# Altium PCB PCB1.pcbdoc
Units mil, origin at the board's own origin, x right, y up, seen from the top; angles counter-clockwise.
Board outline 14460 x 8445 mil, 2 copper layers (Top Layer, Bottom Layer); 15 components, 13 nets, 44 pads, 9 vias.
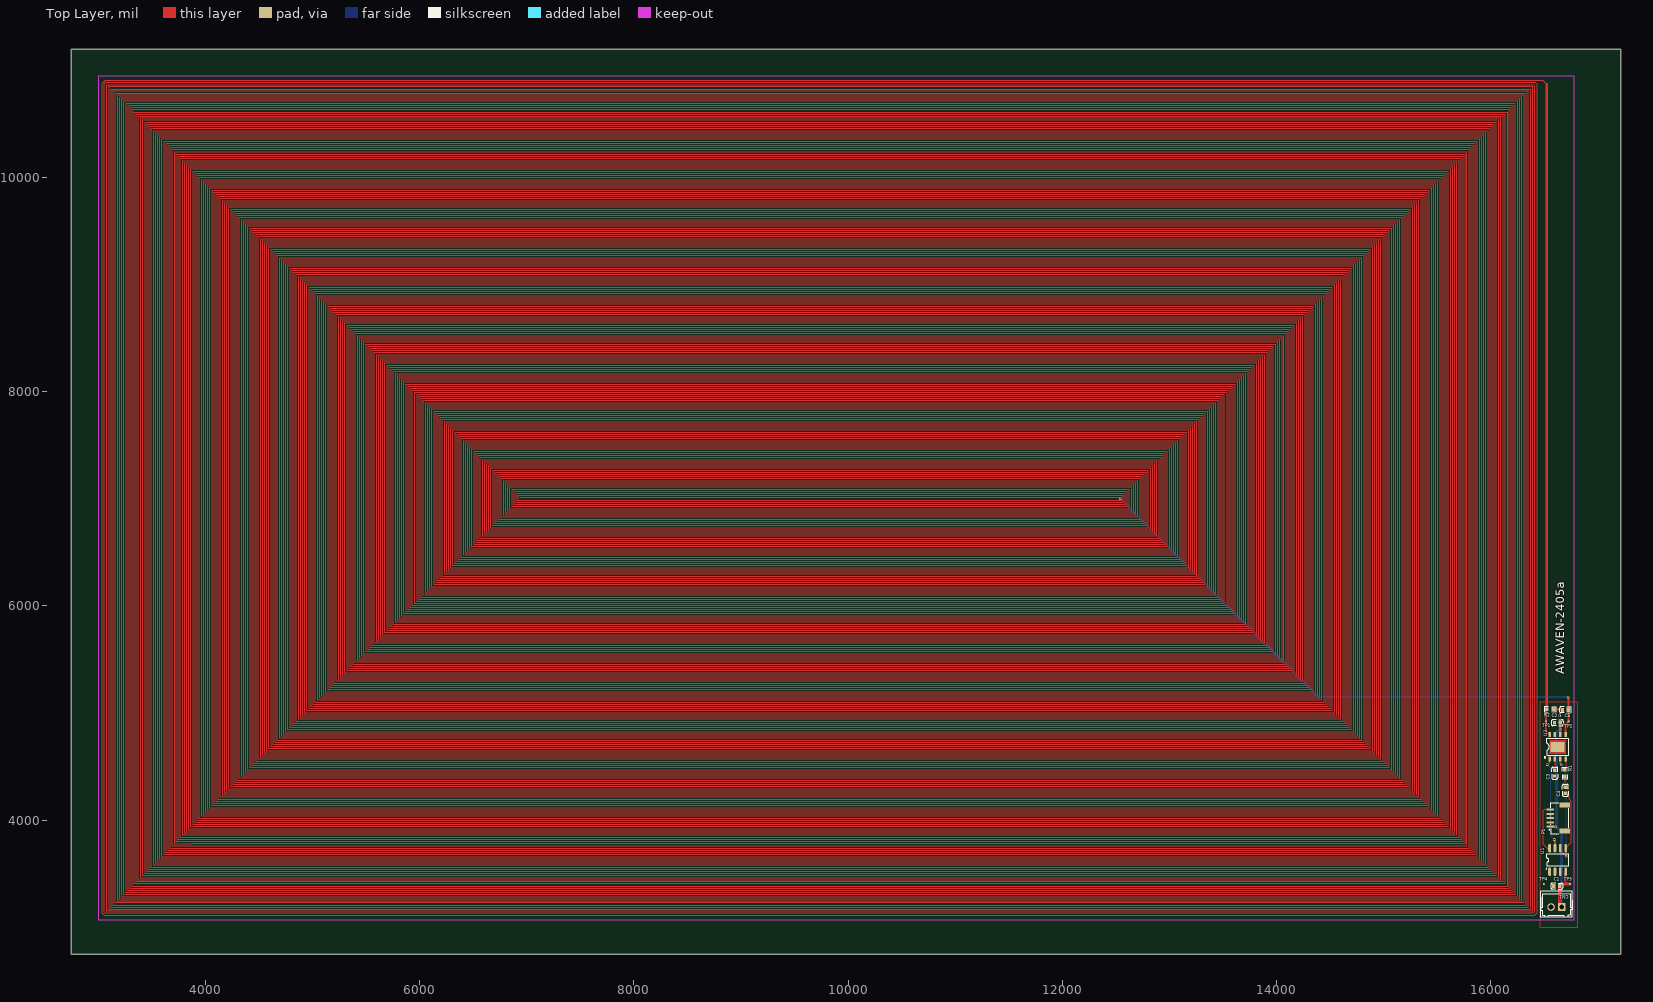
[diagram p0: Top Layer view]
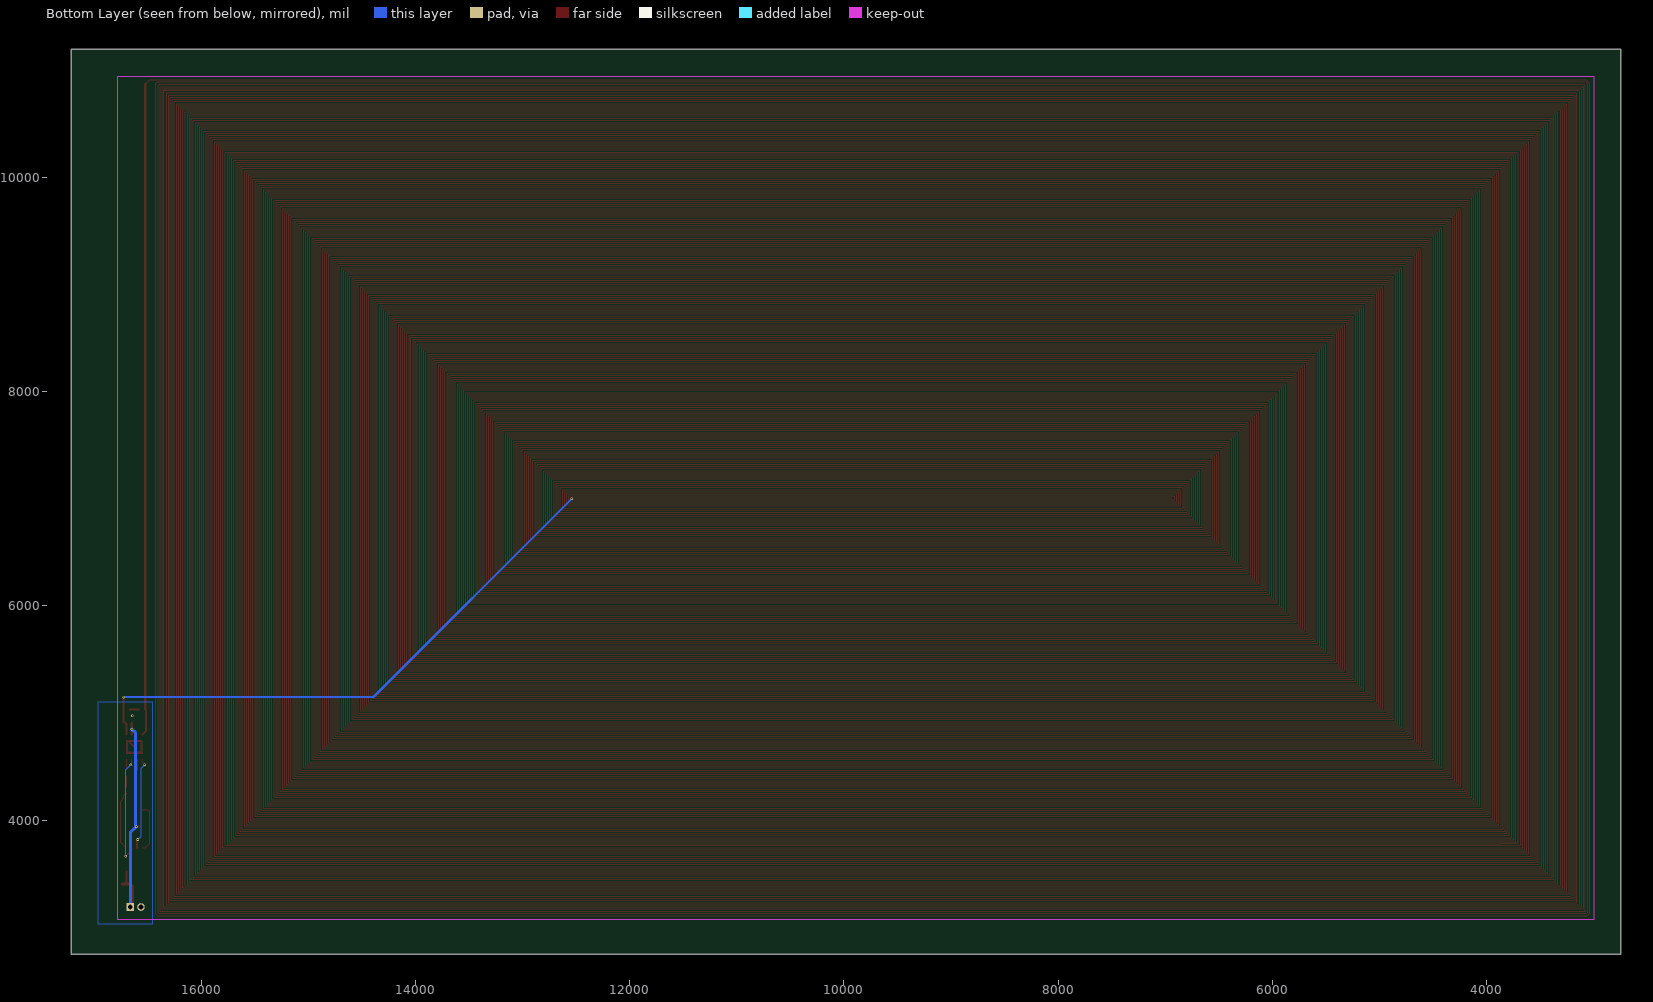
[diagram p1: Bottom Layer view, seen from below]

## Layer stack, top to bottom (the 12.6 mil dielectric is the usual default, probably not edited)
Top Layer: signal copper (thickness not stored)
Dielectric: dielectric 12.6, FR-4, Dk 4.8
Bottom Layer: signal copper (thickness not stored)

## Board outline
17210,2750 2750,2750 2750,11195 17210,11195

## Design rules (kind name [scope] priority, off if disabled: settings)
Clearance copperThickness1oz [All] p1: gap=7 ignorepadtopadclearanceinfootprint=FALSE except(4: Track-Track; 6: Track-SMDPad SMDPad-SMDPad Track-THPad SMDPad-THPad THPad-THPad Track-Via SMDPad-Via THPad-Via Via-Via Track-Fill SMDPad-Fill THPad-Fill Via-Fill Fill-Fill SMDPad-Region THPad-Region Via-Region Fill-Region Region-Region Track-Poly SMDPad-Poly THPad-Poly Via-Poly Fill-Poly Poly-Poly Track-Text SMDPad-Text THPad-Text Via-Text Fill-Text Region-Text Poly-Text Text-Text Track-Hole SMDPad-Hole THPad-Hole Via-Hole Fill-Hole Region-Hole Poly-Hole Text-Hole; 11.8: Track-Region Region-Poly Track-Sheet SMDPad-Sheet THPad-Sheet Via-Sheet Fill-Sheet Region-Sheet Poly-Sheet Text-Sheet Sheet-Hole)
Clearance copperThickness2oz [All] p1: gap=7 ignorepadtopadclearanceinfootprint=FALSE except(6: Track-SMDPad SMDPad-SMDPad Track-THPad SMDPad-THPad THPad-THPad Track-Via SMDPad-Via THPad-Via Via-Via Track-Fill SMDPad-Fill THPad-Fill Via-Fill Fill-Fill SMDPad-Region THPad-Region Via-Region Fill-Region Region-Region Track-Poly SMDPad-Poly THPad-Poly Via-Poly Fill-Poly Poly-Poly Track-Text SMDPad-Text THPad-Text Via-Text Fill-Text Region-Text Poly-Text Text-Text Track-Hole SMDPad-Hole THPad-Hole Via-Hole Fill-Hole Region-Hole Poly-Hole Text-Hole; 8: Track-Track; 11.8: Track-Region Region-Poly Track-Sheet SMDPad-Sheet THPad-Sheet Via-Sheet Fill-Sheet Region-Sheet Poly-Sheet Text-Sheet Sheet-Hole)
DiffPairsRouting differentialPair [All] p1: maxuncoupledlength=10 minlimit=0 maxlimit=5.9843 mostfreqgap=5.9843 toplayer_minwidth=5 toplayer_prefwidth=10 toplayer_maxwidth=100 bottomlayer_minwidth=5 bottomlayer_prefwidth=10 bottomlayer_maxwidth=100
PasteMaskExpansion pasteMaskExpansion [All] p1: expansion=0
PlaneConnect innerPlane [All] p1: planeconnectstyle=Relief reliefexpansion=20 reliefentries=4 reliefconductorwidth=10 reliefairgap=10
PolygonConnect copperRegion [All] p1: connectstyle=Relief reliefentries=4 reliefconductorwidth=10 polygonreliefangle="90 Angle" airgapwidth=10
RoutingVias viaSize [All] p1: viastyle="Through Hole" holewidth=12.0078 minholewidth=11.811 maxholewidth=248.0314 width=24.0158 minwidth=19.685 maxwidth=393.7008
SolderMaskExpansion solderMaskExpansion [All] p1: useseparateexpansions=TRUE expansion=2.0079 expansionbottom=2.0079
Width copperThickness1oz [All] p1: maxlimit=100 minlimit=5 preferedwidth=10
Width copperThickness2oz [All] p1: maxlimit=100 minlimit=8 preferedwidth=10

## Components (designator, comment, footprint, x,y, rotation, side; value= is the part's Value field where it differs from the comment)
C1 "0603B104K500NT" C0603 16615,3385 r0 top
C2 "CAP_0603" C0603 16620,4910 r0 top
C3 "CAP_0603" C0603 16595,4440 r90 top
C4 "CAP_0603" C0603 16695,4280 r90 top
C5 "CAP_0603" C0603 16695,5030 r180 top
CN1 "ZX-XH2.54-2PZZ" CONN-TH_2P-P2.50_HX25003-2A 16610,3190 r180 top
P1 "ZX-SH1.0-5PWT" CONN-SMD_5P-P1.00_MEGASTAR_ZX-SH1.0-5PWT 16620,4020 r90 top
R1 "Res_0603" R0603 16690,4440 r270 top
R2 "Res_0603" R0603 16550,5035 r180 top
TP1 "Test-Point" Test-Point-0.5mm 16515.08,4921.38 r0 top
TP2 "Test-Point" Test-Point-0.5mm 16725.08,4921.38 r0 top
TP3 "Test-Point" Test-Point-0.5mm 16738.16,3405.63 r0 top
TP4 "Test-Point" Test-Point-0.5mm 16493.3,3405.63 r0 top
U1 "CH32V003J4M6_C5346354" SOP-8_L4.9-W3.8-P1.27-LS6.0-BL 16622.05,3630 r0 top
U2 "LTK5128D" ESOP-8_L4.9-W3.9-P1.27-LS6.0-BL-EP 16622.05,4685 r0 top

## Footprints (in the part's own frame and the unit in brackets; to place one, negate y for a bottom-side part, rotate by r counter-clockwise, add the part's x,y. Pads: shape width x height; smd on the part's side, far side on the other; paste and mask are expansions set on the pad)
C0603 [mm]
  rect 0.8x0.9 smd: 1(-0.7,0) 2(0.7,0)
  silkscreen extent -1.41,-0.71 1.39,0.72
CONN-SMD_5P-P1.00_MEGASTAR_ZX-SH1.0-5PWT [mm]
  rect 0.5x1.7 smd: 1(-2,1.7) 2(-1,1.7) 3(0,1.7) 4(1,1.7) 5(2,1.7)
  rect 1.2x2.5 smd: 6(3.1,-1.7) 7(-3.1,-1.7)
  silkscreen extent -3.67,-2.7 3.68,2.21
CONN-TH_2P-P2.50_HX25003-2A [mm]
  rect 1.8x1.8 hole 1.1: 1(-1.25,0)
  round 1.8 hole 1.1: 2(1.25,0)
  silkscreen extent -3.75,-3.7 3.75,2.41
ESOP-8_L4.9-W3.9-P1.27-LS6.0-BL-EP [mm]
  rect 0.6x1.2 smd: 1(-1.905,-2.908) 2(-0.635,-2.908) 3(0.635,-2.908) 4(1.905,-2.908) 5(1.905,2.908) 6(0.635,2.908) 7(-0.635,2.908) 8(-1.905,2.908)
  rect 3.3x2.4 smd: 9(0,0)
  silkscreen extent -3.2,-2.67 2.55,2.05
R0603 [mil]
  rect 31.75x34.02 smd: 1(-29.66,0) 2(29.66,0)
  silkscreen extent -55,-26 55,26
SOP-8_L4.9-W3.8-P1.27-LS6.0-BL [mil]
  oval 25.59x80 smd: 1(-75,-110.08) 2(-25,-110.08) 3(25,-110.08) 4(75,-110.08) 5(75,110.08) 6(25,110.08) 7(-25,110.08) 8(-75,110.08)
  silkscreen extent -108,-85 101,57
Test-Point-0.5mm [mm]
  round 0.5 smd: 1(0,0)

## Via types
v1: diameter 24.02, hole 12.01, Top Layer to Bottom Layer, 9 vias

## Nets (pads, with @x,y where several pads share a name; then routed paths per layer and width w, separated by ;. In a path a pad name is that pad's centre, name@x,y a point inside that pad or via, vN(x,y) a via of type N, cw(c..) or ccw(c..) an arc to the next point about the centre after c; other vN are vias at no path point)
$1N468: C3.2 U2.2 | length 103.8
  Top Layer w10: C3.2 16597.05,4469.61 U2.2
$1N596: C4.1 U1.5 | length 557.1
  Top Layer w10: C4.1 16725,4222.44 16725,4203.7 16750,4178.7 16750,3793.03 U1.5
$1N669: C4.2 R1.2 | length 104.9
  Top Layer w10: R1.2 16695,4405.34 C4.2
$1N795: C5.2 R2.1 | length 89.9
  Top Layer w19.68: R2.1 16662.44,5035 C5.2
DIO: P1.5 U1.8 | length 459.5
  Top Layer w10: U1.8 16524.92,3740.08 16485,3780 16485,4088.74 16495,4098.74 P1.5
GND: C1.1 C2.1 C3.1 CN1.2 P1.4 P1.6 P1.7 TP4.1 U1.2 U2.7 U2.9 | length 571.1
  Top Layer w19.68: U2.9 16675,4737.95 16675,4740 16555,4740 16555,4635 16550,4630 16685,4630 16690,4625 16690,4745
  other v1: 16640,4975
IN: R1.1 U2.4 | length 103.8
  Top Layer w10: R1.1 16697.05,4476.71 U2.4
MODE: U1.6 U2.3 | length 1028.3
  Top Layer w10: U1.6 16647.05,3718.62 v1(16701.83,3663.84) ; U2.3 16647.05,4525.3 v1(16656.14,4516.21)
  Bottom Layer w10: v1(16656.14,4516.21) 16701.83,4470.52 v1(16701.83,3663.84)
OV: C5.1 R2.2 TP1.1 TP2.1 U2.5 U2.8 | length 5333328.9
  Top Layer w10: 3070,3130 3059.06,3140.94 3059.06,10874.06 3070.94,10885.94 16415,10885.94 ; 3070.04,3130.04 16391.66,3130.04 16405,3143.38 ; 3098.43,3169.41 16365,3169.41 ; 3098.43,3175 3098.43,10846.57 16384.25,10846.57 16385.83,10845 16385.83,3150 3080,3150 3080,10860 3085,10865 16396.8,10865 16405.51,10856.29 16405.51,3143.38 ; 3137.8,3208.78 16325,3208.78 ; 3137.8,3210 3137.8,10803.19 3141.81,10807.2 16346.46,10807.2 16346.46,3190 3118.11,3190 3118.11,10825 16366.14,10825 16366.14,3169.41 ; 3157.48,3228.46 3157.48,10785 3160,10787.52 16326.77,10787.52 ; 3160,3228.46 16305,3228.46 ; 3177.17,10767.83 3177.17,3248.15 16285,3248.15 ; 3180,10767.83 16303.86,10767.83 16306.69,10765 16306.69,3228.46 ; 3196.85,10748.15 3196.85,3267.83 16265,3267.83 ; 3200,10748.15 16287.4,10748.15 16287.4,3248.15 ; 3236.22,3307.2 16228.35,3307.2 16228.35,10689.09 3255.91,10689.09 3255.91,3326.89 16208.66,3326.89 16208.66,10668.66 ; 3236.22,3308.78 3236.22,10709.17 16248.03,10709.17 16248.03,3287.52 ; 3275.59,3346.57 16188.98,3346.57 16188.98,10649.72 ; 3275.59,3350 3275.59,10669.41 16208.66,10669.41 ; 3295,10649.72 3295.28,10649.72 ; 3374.02,10570.98 3374.02,3445.98 3375,3445 16090.55,3445 16090.55,10551.3 3393.7,10551.3 3393.7,3465 ; 3375,10570.98 16110.24,10570.98 16110.24,3425.32 3354.33,3425.32 3354.33,10590.67 16129.92,10590.67 16129.92,3405.63 3334.65,3405.63 3334.65,10610.35 16149.61,10610.35 16149.61,3385.94 ; 3393.7,3464.68 16070,3464.68 16070.87,3465.55 16070.87,10531.61 3413.39,10531.61 3413.39,3485 ; 3413.39,3484.37 16050,3484.37 ; 3433.07,10511.93 3433.07,3504.06 16030,3504.06 ; 3435,10511.93 16051.18,10511.93 16051.18,3484.37 ; 3870,3780 3870,3779.65 ; 6937.01,7007.99 12547.24,7007.99 12547.24,6988.31 6917.32,6988.31 6917.32,7027.68 12566.93,7027.68 12566.93,6968.62 6897.64,6968.62 6897.64,7047.36 12586.61,7047.36 12586.61,6948.94 6877.95,6948.94 6877.95,7067.05 12606.3,7067.05 12606.3,6929.25 6858.27,6929.25 6858.27,7086.73 12625.98,7086.73 12625.98,6909.57 6838.58,6909.57 6838.58,7106.42 12645.67,7106.42 12645.67,6889.88 6818.9,6889.88 6818.9,7126.1 12664.25,7126.1 12665.35,7125 ; 12665.35,7126.1 12665.35,7125 ; 15785,10335 15785.24,10334.76 ; 16031.5,3504.06 16031.5,10490 ; 16031.5,10492.24 3452.76,10492.24 3452.76,3523.74 16011.81,3523.74 16011.81,10472.56 3472.44,10472.56 3472.44,3543.43 15992.13,3543.43 15992.13,10452.87 3492.13,10452.87 3492.13,3563.11 15972.44,3563.11 15972.44,10433.19 3511.81,10433.19 3511.81,3582.8 15952.76,3582.8 15952.76,10413.5 3531.5,10413.5 3531.5,3602.48 15933.07,3602.48 15933.07,10393.82 3551.18,10393.82 3551.18,3622.17 15913.39,3622.17 15913.39,10374.13 3570.87,10374.13 3570.87,3641.85 15893.7,3641.85 15893.7,10354.45 3590.55,10354.45 3590.55,3661.54 15874.02,3661.54 15874.02,10334.76 15785.24,10334.76 ; 16150,3385.94 16149.61,3385.94 ; 16169.29,10630 16169.29,3366.26 3295.28,3366.26 3295.28,10649.72 ; 16169.29,10630.04 3314.96,10630.04 3314.96,3385.94 16149.61,3385.94 ; 16188.98,10650 16188.98,10649.72 ; 16245,3287.52 3219.02,3287.52 3216.54,3290 3216.54,10728.46 16267.32,10728.46 ; 16267.32,3267.83 16267.32,10724.92 ; 16326.77,3208.78 16326.77,10785 ; 16415,10885 16425,10875 16425,3130 16405.35,3110.35 3059.65,3110.35 3040,3130 3040,10880 3065,10905 16485,10905 16520.34,10869.66 ; TP2.1@16722.56,4921.38 TP2.1 ; 3295.28,10649.72 16188.98,10649.72 ; 3870,3779.65 3708.66,3779.65 3708.66,10236.34 15775.59,10236.34 15775.59,3759.96 3688.98,3759.96 3688.98,10256.02 15795.28,10256.02 15795.28,3740.28 3669.29,3740.28 3669.29,10275.71 15814.96,10275.71 15814.96,3720.59 3649.61,3720.59 3649.61,10295.39 15834.65,10295.39 15834.65,3700.91 3629.92,3700.91 3629.92,10315.08 15854.33,10315.08 15854.33,3681.22 3610.24,3681.22 3610.24,10334.76 15785.24,10334.76 ; 3870,3779.65 15755.91,3779.65 15755.91,10216.65 3728.35,10216.65 3728.35,3799.33 15736.22,3799.33 15736.22,10196.97 3748.03,10196.97 3748.03,3819.02 15716.54,3819.02 15716.54,10177.28 3767.72,10177.28 3767.72,3838.7 15696.85,3838.7 15696.85,10157.6 3787.4,10157.6 3787.4,3858.39 15677.17,3858.39 15677.17,10137.91 3807.09,10137.91 3807.09,3878.07 15657.48,3878.07 15657.48,10118.23 3826.77,10118.23 3826.77,3897.76 15637.8,3897.76 15637.8,10098.54 3846.46,10098.54 3846.46,3917.44 15618.11,3917.44 15618.11,10078.86 3866.14,10078.86 3866.14,3937.13 15598.43,3937.13 15598.43,10059.17 3885.83,10059.17 3885.83,3956.81 15578.74,3956.81 15578.74,10039.49 3905.51,10039.49 3905.51,3976.5 15559.06,3976.5 15559.06,10019.8 3925.2,10019.8 3925.2,3996.18 15539.37,3996.18 15539.37,10000.12 3944.88,10000.12 3944.88,4015.87 15519.68,4015.87 15519.68,9980.43 3964.57,9980.43 3964.57,4035.55 15500,4035.55 15500,9960.75 3984.25,9960.75 3984.25,4055.24 15480.32,4055.24 15480.32,9941.06 4003.94,9941.06 4003.94,4074.92 15460.63,4074.92 15460.63,9921.38 4023.62,9921.38 4023.62,4094.61 15440.94,4094.61 15440.94,9901.69 4043.31,9901.69 4043.31,4114.29 15421.26,4114.29 15421.26,9882.01 4062.99,9882.01 4062.99,4133.98 15401.57,4133.98 15401.57,9862.32 4082.68,9862.32 4082.68,4153.66 15381.89,4153.66 15381.89,9842.64 4102.36,9842.64 4102.36,4173.35 15362.2,4173.35 15362.2,9822.95 4122.05,9822.95 4122.05,4193.03 15342.52,4193.03 15342.52,9803.27 4141.73,9803.27 4141.73,4212.72 15322.83,4212.72 15322.83,9783.58 4161.42,9783.58 4161.42,4232.4 15303.15,4232.4 15303.15,9763.9 4181.1,9763.9 4181.1,4252.09 15283.46,4252.09 15283.46,9744.21 4200.79,9744.21 4200.79,4271.77 15263.78,4271.77 15263.78,9724.53 4220.47,9724.53 4220.47,4291.46 15244.09,4291.46 15244.09,9704.84 4240.16,9704.84 4240.16,4311.14 15224.41,4311.14 15224.41,9685.16 4259.84,9685.16 4259.84,4330.83 15204.72,4330.83 15204.72,9665.47 4279.53,9665.47 4279.53,4350.51 15185.04,4350.51 15185.04,9645.79 4299.21,9645.79 4299.21,4370.2 15165.35,4370.2 15165.35,9626.1 4318.9,9626.1 4318.9,4389.88 15145.67,4389.88 15145.67,9606.42 4338.58,9606.42 4338.58,4409.57 15125.98,4409.57 15125.98,9586.73 4358.27,9586.73 4358.27,4429.25 15106.3,4429.25 15106.3,9567.05 4377.95,9567.05 4377.95,4448.94 15086.61,4448.94 15086.61,9547.36 4397.64,9547.36 4397.64,4468.62 15066.93,4468.62 15066.93,9527.68 4417.32,9527.68 4417.32,4488.31 15047.24,4488.31 15047.24,9507.99 4437.01,9507.99 4437.01,4507.99 15027.56,4507.99 15027.56,9488.31 4456.69,9488.31 4456.69,4527.68 15007.87,4527.68 15007.87,9468.62 4476.38,9468.62 4476.38,4547.36 14988.19,4547.36 14988.19,9448.94 4496.06,9448.94 4496.06,4567.05 14968.5,4567.05 14968.5,9429.25 4515.75,9429.25 4515.75,4586.73 14948.82,4586.73 14948.82,9409.57 4535.43,9409.57 4535.43,4606.42 14929.13,4606.42 14929.13,9389.88 4555.12,9389.88 4555.12,4626.1 14909.45,4626.1 14909.45,9370.2 4574.8,9370.2 4574.8,4645.79 14889.76,4645.79 14889.76,9350.51 4594.49,9350.51 4594.49,4665.47 14870.08,4665.47 14870.08,9330.83 4614.17,9330.83 4614.17,4685.16 14850.39,4685.16 14850.39,9311.14 4633.86,9311.14 4633.86,4704.84 14830.71,4704.84 14830.71,9291.46 4653.54,9291.46 4653.54,4724.53 14811.02,4724.53 14811.02,9271.77 4673.23,9271.77 4673.23,4744.21 14791.34,4744.21 14791.34,9252.09 4692.91,9252.09 4692.91,4763.9 14771.65,4763.9 14771.65,9232.4 4712.6,9232.4 4712.6,4783.58 14751.97,4783.58 14751.97,9212.72 4732.28,9212.72 4732.28,4803.27 14732.28,4803.27 14732.28,9193.03 4751.97,9193.03 4751.97,4822.95 14712.6,4822.95 14712.6,9173.35 4771.65,9173.35 4771.65,4842.64 14692.91,4842.64 14692.91,9153.66 4791.34,9153.66 4791.34,4862.32 14673.23,4862.32 14673.23,9133.98 4811.02,9133.98 4811.02,4882.01 14653.54,4882.01 14653.54,9114.29 4830.71,9114.29 4830.71,4901.69 14633.86,4901.69 14633.86,9094.61 4850.39,9094.61 4850.39,4921.38 14614.17,4921.38 14614.17,9074.92 4870.08,9074.92 4870.08,4941.06 14594.49,4941.06 14594.49,9055.24 4889.76,9055.24 4889.76,4960.75 14574.8,4960.75 14574.8,9035.55 4909.45,9035.55 4909.45,4980.43 14555.12,4980.43 14555.12,9015.87 4929.13,9015.87 4929.13,5000.12 14535.43,5000.12 14535.43,8996.18 4948.82,8996.18 4948.82,5019.8 14515.75,5019.8 14515.75,8976.5 4968.5,8976.5 4968.5,5039.49 14496.06,5039.49 14496.06,8956.81 4988.19,8956.81 4988.19,5059.17 14476.38,5059.17 14476.38,8937.13 5007.87,8937.13 5007.87,5078.86 14456.69,5078.86 14456.69,8917.44 5027.56,8917.44 5027.56,5098.54 14437.01,5098.54 14437.01,8897.76 5047.24,8897.76 5047.24,5118.23 14417.32,5118.23 14417.32,8878.07 5066.93,8878.07 5066.93,5137.91 14397.64,5137.91 14397.64,8858.39 5086.61,8858.39 5086.61,5157.6 14377.95,5157.6 14377.95,8838.7 5106.3,8838.7 5106.3,5177.28 14358.27,5177.28 14358.27,8819.02 5125.98,8819.02 5125.98,5196.97 14338.58,5196.97 14338.58,8799.33 5145.67,8799.33 5145.67,5216.65 14318.9,5216.65 14318.9,8779.65 5165.35,8779.65 5165,5236.34 14299.21,5236.34 14299.21,8759.96 5185.04,8759.96 5185.04,5256.02 14279.53,5256.02 14279.53,8740.28 5204.72,8740.28 5204.72,5275.71 14259.84,5275.71 14259.84,8720.59 5224.41,8720.59 5224.41,5295.39 14240.16,5295.39 14240.16,8700.91 5244.09,8700.91 5244.09,5315.08 14220.47,5315.08 14220.47,8681.22 5263.78,8681.22 5263.78,5334.76 14200.79,5334.76 14200.79,8661.54 5283.46,8661.54 5283.46,5354.45 14181.1,5354.45 14181.1,8641.85 5303.15,8641.85 5303.15,5374.13 14161.42,5374.13 14161.42,8622.17 5322.83,8622.17 5322.83,5393.82 14141.73,5393.82 14141.73,8602.48 5342.52,8602.48 5342.52,5413.5 14122.05,5413.5 14122.05,8582.8 5362.2,8582.8 5362.2,5433.19 14102.36,5433.19 14102.36,8563.11 5381.89,8563.11 5381.89,5452.87 14082.68,5452.87 14082.68,8543.43 5401.57,8543.43 5401.57,5472.56 14062.99,5472.56 14062.99,8523.74 5421.26,8523.74 5421.26,5492.24 14045,5492.24 14045,8504.06 5440.94,8504.06 5440.94,5511.93 14023.62,5511.93 14023.62,8484.37 5460.63,8484.37 5460.63,5531.61 14003.94,5531.61 14003.94,8464.68 5480.31,8464.68 5480.31,5551.3 13984.25,5551.3 13984.25,8445 5500,8445 5500,5570.98 13964.57,5570.98 13964.57,8425.32 5519.69,8425.32 5519.69,5590.67 13944.88,5590.67 13944.88,8405.63 5539.37,8405.63 5539.37,5610.35 13925.2,5610.35 13925.2,8385.94 5559.06,8385.94 5559.06,5630.04 13905.51,5630.04 13905.51,8366.26 5578.74,8366.26 5578.74,5649.72 13885.83,5649.72 13885.83,8346.57 5598.43,8346.57 5598.43,5669.41 13866.14,5669.41 13866.14,8326.89 5618.11,8326.89 5618.11,5689.09 13846.46,5689.09 13846.46,8307.2 5637.8,8307.2 5637.8,5708.78 13826.77,5708.78 13826.77,8287.52 5657.48,8287.52 5657.48,5728.46 13807.09,5728.46 13807.09,8267.83 5677.17,8267.83 5677.17,5748.15 13787.4,5748.15 13787.4,8248.15 5696.85,8248.15 5696.85,5767.83 13767.72,5767.83 13767.72,8228.46 5716.54,8228.46 5716.54,5787.52 13748.03,5787.52 13748.03,8208.78 5736.22,8208.78 5736.22,5807.2 13728.35,5807.2 13728.35,8189.09 5755.91,8189.09 5755.91,5826.89 13708.66,5826.89 13708.66,8169.41 5775.59,8169.41 5775.59,5846.57 13688.98,5846.57 13688.98,8149.72 5795.28,8149.72 5795.28,5866.26 13669.29,5866.26 13669.29,8130.04 5814.96,8130.04 5814.96,5885.94 13649.61,5885.94 13649.61,8110.35 5834.65,8110.35 5834.65,5905.63 13629.92,5905.63 13629.92,8090.67 5854.33,8090.67 5854.33,5925.31 13610.24,5925.31 13610.24,8070.98 5874.02,8070.98 5874.02,5945 13590.55,5945 13590.55,8051.3 5893.7,8051.3 5893.7,5964.69 13570.87,5964.69 13570.87,8031.61 5913.39,8031.61 5913.39,5984.37 13551.18,5984.37 13551.18,8011.93 5933.07,8011.93 5933.07,6004.06 13531.5,6004.06 13531.5,7992.24 5952.76,7992.24 5952.76,6023.74 13511.81,6023.74 13511.81,7972.56 5972.44,7972.56 5972.44,6043.43 13492.13,6043.43 13492.13,7952.87 5992.13,7952.87 5992.13,6063.11 13472.44,6063.11 13472.44,7933.19 6011.81,7933.19 6011.81,6082.8 13452.76,6082.8 13452.76,7913.5 6031.5,7913.5 6031.5,6102.48 13433.07,6102.48 13433.07,7893.82 6051.18,7893.82 6051.18,6122.17 13413.39,6122.17 13413.39,7874.13 6070.87,7874.13 6070.87,6141.85 13393.7,6141.85 13393.7,7854.45 6090.55,7854.45 6090.55,6161.54 13374.02,6161.54 13374.02,7834.76 6110.24,7834.76 6110.24,6181.22 13354.33,6181.22 13354.33,7815.08 6129.92,7815.08 6129.92,6200.91 13334.65,6200.91 13334.65,7795.39 6149.61,7795.39 6149.61,6220.59 13314.96,6220.59 13314.96,7775.71 6169.29,7775.71 6169.29,6240.28 13295.28,6240.28 13295.28,7756.02 6188.98,7756.02 6188.98,6259.96 13275.59,6259.96 13275.59,7736.34 6208.66,7736.34 6208.66,6279.65 13255.91,6279.65 13255.91,7716.65 6228.35,7716.65 6228.35,6299.33 13236.22,6299.33 13236.22,7696.97 6248.03,7696.97 6248.03,6319.02 13216.54,6319.02 13216.54,7677.28 6267.72,7677.28 6267.72,6338.7 13196.85,6338.7 13196.85,7657.6 6287.4,7657.6 6287.4,6358.39 13177.17,6358.39 13177.17,7637.91 6307.09,7637.91 6307.09,6378.07 13157.48,6378.07 13157.48,7618.23 6326.77,7618.23 6326.77,6397.76 13137.8,6397.76 13137.8,7598.54 6346.46,7598.54 6346.46,6417.44 13118.11,6417.44 13118.11,7578.86 6366.14,7578.86 6366.14,6437.13 13098.43,6437.13 13098.43,7559.17 6385.83,7559.17 6385.83,6456.81 13078.74,6456.81 13078.74,7539.49 6405.51,7539.49 6405.51,6476.5 13059.06,6476.5 13059.06,7519.8 6425.2,7519.8 6425.2,6496.18 13039.37,6496.18 13039.37,7500.12 6444.88,7500.12 6444.88,6515.87 13019.68,6515.87 13019.68,7480.43 6464.57,7480.43 6464.57,6535.55 13000,6535.55 13000,7460.75 6484.25,7460.75 6484.25,6555.24 12980.32,6555.24 12980.32,7441.06 6503.94,7441.06 6503.94,6574.92 12960.63,6574.92 12960.63,7421.38 6523.62,7421.38 6523.62,6594.61 12940.94,6594.61 12940.94,7401.69 6543.31,7401.69 6543.31,6614.29 12921.26,6614.29 12921.26,7382.01 6562.99,7382.01 6562.99,6633.98 12901.57,6633.98 12901.57,7362.32 6582.68,7362.32 6582.68,6653.66 12881.89,6653.66 12881.89,7342.64 6602.36,7342.64 6602.36,6673.35 12862.2,6673.35 12862.2,7322.95 6622.05,7322.95 6622.05,6693.03 12842.52,6693.03 12842.52,7303.27 6641.73,7303.27 6641.73,6712.72 12822.83,6712.72 12822.83,7283.58 6661.42,7283.58 6661.42,6732.4 12803.15,6732.4 12803.15,7263.9 6681.1,7263.9 6681.1,6752.09 12783.46,6752.09 12783.46,7244.21 6700.79,7244.21 6700.79,6771.77 12763.78,6771.77 12763.78,7224.53 6720.47,7224.53 6720.47,6791.46 12744.09,6791.46 12744.09,7204.84 6740.16,7204.84 6740.16,6811.14 12724.41,6811.14 12724.41,7185.16 6759.84,7185.16 6759.84,6830.83 12704.72,6830.83 12704.72,7165.47 6779.53,7165.47 6779.53,6850.51 12685.04,6850.51 12685.04,7145.79 6799.21,7145.79 6799.21,6870.2 12665.35,6870.2 12665.35,7125
  Top Layer w19.68: 16520.34,10869.66 R2.2 16515.08,5029.74 TP1.1 16515.08,4831.47 U2.8 ; U2.5 16697.05,4895.87 16722.56,4921.38 C5.1 v1@16722.56,5145
  Bottom Layer w19.68: v1(12540,7000) 14390,5150 v1(16720,5150)
SD: U1.7 U2.1 | length 869.4
  Top Layer w10: v1(16525,4520) 16547.05,4542.05 U2.1
  Top Layer w19.68: v1(16590,3820) 16597.05,3812.95 U1.7
  Bottom Layer w10: v1(16525,4520) 16560,4485 16560,3850 v1(16590,3820)
URX: P1.3
UTX: P1.2
VCC: C1.2 C2.2 CN1.1 P1.1 TP3.1 U1.4 U2.6 | length 2267.5
  Top Layer w19.68: P1.1@16568.07,3941.26 16569.33,3940 v1(16605,3940) ; U2.6 16647.05,4909.49 C2.2 ; 16697.05,3405.63 U1.4
  Top Layer w29.53: CN1.1 16642.56,3206.65 C1.2 16663.19,3405.63 16697.05,3405.63 TP3.1
  Bottom Layer w29.53: v1(16645,4850) 16610.47,4815.47 16610.47,3945.47 v1(16605,3940) 16659.21,3885.79 CN1.1
pads on no net: U1.1 U1.3

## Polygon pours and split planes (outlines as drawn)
GND on Top Layer (solid, remove dead copper, pour order 0): 16455,3000 16810,3000 16810,5100 16455,5100
GND on Bottom Layer (solid, remove dead copper, pour order 4): 16455,3030 16960,3030 16960,5105 16455,5105

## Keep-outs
Board Outline Layer:
  lines w10: 3000,3070.98 16779.53,3070.98 16779.53,10945 3000,10945 3000,3070.98

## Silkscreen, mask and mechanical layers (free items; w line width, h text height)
Top Silkscreen Layer:
  text "AWAVEN-2405a" at 16683.36,5362.57 h77.88 r90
